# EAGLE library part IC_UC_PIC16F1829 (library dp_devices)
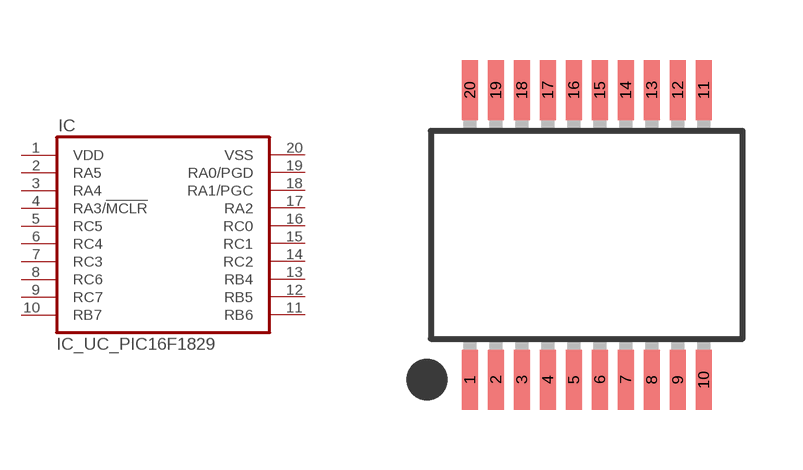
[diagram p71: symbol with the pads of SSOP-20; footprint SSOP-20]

Designator prefix IC

## IC_UC_PIC16F1829-SSOP-20  [SSOP-20]
1  VDD  pwr
2  RA5
3  RA4
4  RA3/!MCLR  in
5  RC5
6  RC4
7  RC3
8  RC6
9  RC7
10  RB7
11  RB6
12  RB5
13  RB4
14  RC2
15  RC1
16  RC0
17  RA2
18  RA1/PGC
19  RA0/PGD
20  VSS  pwr

## Footprint SSOP-20 (pad centres in mm)
smd 0.4 x 1.5: 1 -2.925,-3.625; 2 -2.275,-3.625; 3 -1.625,-3.625; 4 -0.975,-3.625; 5 -0.325,-3.625; 6 0.325,-3.625; 7 0.975,-3.625; 8 1.625,-3.625; 9 2.275,-3.625; 10 2.925,-3.625; 11 2.925,3.625; 12 2.275,3.625; 13 1.625,3.625; 14 0.975,3.625; 15 0.325,3.625; 16 -0.325,3.625; 17 -0.975,3.625; 18 -1.625,3.625; 19 -2.275,3.625; 20 -2.925,3.625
